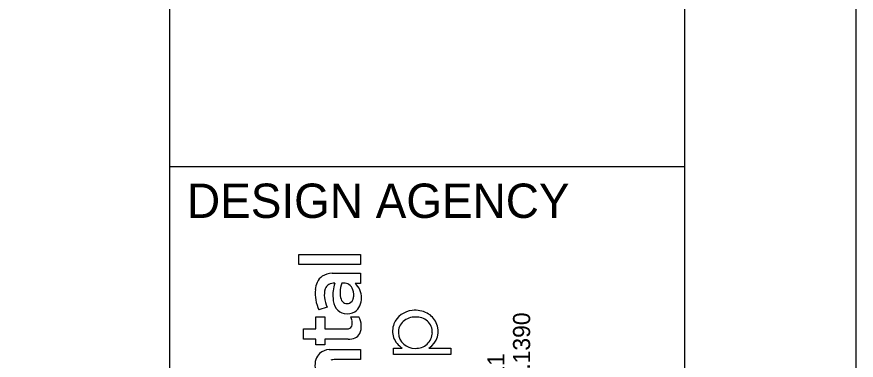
# Model space of a CAD drawing. Extents: x -5960 to 34, y -2569 to 22.
# Drawn here: x 31.554 to 34, y 3.936 to 4.936 of the extents above; entities that cross this region are included whole.
import ezdxf

# ---------------------------------------------------------------- set-up
doc = ezdxf.new("R2010")
doc.units = 0
for name, color, linetype in [('GT_Instrumented_Soil_Boring', 7, 'Continuous'), ('SV_X_Mon_Cells_Found', 7, 'Continuous'), ('SV_X_Shot_Marker', 7, 'Continuous')]:
    doc.layers.add(name, color=color, linetype=linetype)

msp = doc.modelspace()

# ---------------------------------------------------------------- linework, layer by layer
at = {"layer": 'GT_Instrumented_Soil_Boring'}
for p, q in [((32.3756, 4.2141), (32.3756, 4.244)), ((32.3756, 4.244), (32.5557, 4.244)), ((32.5557, 4.244), (32.5557, 4.2141)), ((32.5557, 4.2141), (32.3756, 4.2141)), ((32.4727, 4.189), (32.5555, 4.1892)), ((32.5555, 4.1892), (32.5557, 4.1596)), ((32.5557, 4.1596), (32.5397, 4.1596)), ((32.4582, 4.0904), (32.4343, 4.0823)), ((32.4254, 4.027), (32.4255, 4.0621)), ((32.4255, 4.0621), (32.4511, 4.0621)), ((32.4511, 4.0621), (32.4512, 4.027)), ((32.527, 4.0616), (32.5511, 4.0616)), ((32.3896, 3.9972), (32.3896, 4.027)), ((32.3896, 4.027), (32.4254, 4.027)), ((32.4512, 4.027), (32.515, 4.027)), ((32.515, 4.027), (32.52, 4.0275)), ((32.4254, 3.9972), (32.3896, 3.9972)), ((32.4254, 3.9807), (32.4254, 3.9972)), ((32.5197, 3.9972), (32.4511, 3.9972)), ((32.4511, 3.9972), (32.4511, 3.9807)), ((32.4511, 3.9807), (32.4254, 3.9807)), ((32.4644, 3.9669), (32.4729, 3.9673)), ((32.4729, 3.9673), (32.5557, 3.9673)), ((32.5557, 3.9673), (32.5557, 3.9375)), ((32.6515, 3.9521), (32.6515, 3.9711)), ((32.6515, 3.9711), (32.6771, 3.9711)), ((32.7549, 3.9713), (32.8186, 3.9711)), ((32.8186, 3.9711), (32.8184, 3.9521)), ((32.8184, 3.9521), (32.6515, 3.9521)), ((32.5557, 3.9375), (32.4814, 3.9375))]:
    msp.add_line(p, q, dxfattribs=at)
msp.add_lwpolyline([(32.3756, 4.2141), (32.3756, 4.244), (32.5557, 4.244), (32.5557, 4.2141)], close=True, dxfattribs=at)
for points in [[(32.4727, 4.189), (32.5555, 4.1892), (32.5557, 4.1596)], [(32.5557, 4.1596), (32.5397, 4.1596)], [(32.4582, 4.0904), (32.4343, 4.0823)], [(32.5197, 3.9972), (32.4511, 3.9972), (32.4511, 3.9807), (32.4254, 3.9807), (32.4254, 3.9972), (32.3896, 3.9972), (32.3896, 4.027), (32.4254, 4.027), (32.4255, 4.0621), (32.4511, 4.0621), (32.4512, 4.027), (32.515, 4.027), (32.52, 4.0275)], [(32.527, 4.0616), (32.5511, 4.0616)], [(32.4644, 3.9669), (32.4729, 3.9673), (32.5557, 3.9673), (32.5557, 3.9375), (32.4814, 3.9375)], [(32.7549, 3.9713), (32.8186, 3.9711), (32.8184, 3.9521), (32.6515, 3.9521)], [(32.6515, 3.9521), (32.6515, 3.9711), (32.6771, 3.9711)]]:
    msp.add_lwpolyline(points, dxfattribs=at)
for centre, radius, start, end in [((32.4745, 4.1326), 0.0565, 91.8942, 122.6317), ((32.4745, 4.1326), 0.0565, 91.8942, 122.6317), ((32.4882, 4.1361), 0.0646, 155.9764, 175.3149), ((32.4882, 4.1361), 0.0646, 155.9764, 175.3149), ((32.4685, 4.1447), 0.043, 124.537, 155.6594), ((32.4685, 4.1447), 0.043, 124.537, 155.6594), ((32.4779, 4.1278), 0.0321, 85.3802, 116.6222), ((32.4779, 4.1278), 0.0321, 85.3802, 116.6222), ((32.5879, 4.1251), 0.1129, 162.0821, 184.5285), ((32.5879, 4.1251), 0.1129, 162.0821, 184.5285), ((32.5801, 4.1313), 0.0841, 159.8366, 178.0362), ((32.5801, 4.1313), 0.0841, 159.8366, 178.0362), ((32.5051, 4.1074), 0.053, 79.6696, 94.2322), ((32.5051, 4.1074), 0.053, 79.6696, 94.2322), ((32.5089, 4.1364), 0.0238, 56.8913, 76.2149), ((32.5089, 4.1364), 0.0238, 56.8913, 76.2149), ((32.5055, 4.1191), 0.0529, 358.0746, 49.762), ((32.5055, 4.1191), 0.0529, 358.0746, 49.762), ((32.5364, 4.1308), 0.113, 174.6101, 205.3899), ((32.5364, 4.1308), 0.113, 174.6101, 205.3899), ((32.5076, 4.1265), 0.0576, 163.1369, 188.1675), ((32.5076, 4.1265), 0.0576, 163.1369, 188.1675), ((32.4753, 4.1356), 0.024, 119.4252, 161.6629), ((32.4753, 4.1356), 0.024, 119.4252, 161.6629), ((32.5466, 4.1303), 0.0506, 175.5903, 199.8857), ((32.5466, 4.1303), 0.0506, 175.5903, 199.8857), ((32.5052, 4.1318), 0.0297, 17.5984, 55.7282), ((32.5052, 4.1318), 0.0297, 17.5984, 55.7282), ((32.4916, 4.1264), 0.0443, 345.9408, 18.9919), ((32.4916, 4.1264), 0.0443, 345.9408, 18.9919), ((32.5473, 4.1297), 0.0973, 186.7598, 203.7981), ((32.5473, 4.1297), 0.0973, 186.7598, 203.7981), ((32.5328, 4.1187), 0.0575, 182.5676, 213.7144), ((32.5328, 4.1187), 0.0575, 182.5676, 213.7144), ((32.5164, 4.1189), 0.0184, 198.2844, 293.3081), ((32.5164, 4.1189), 0.0184, 198.2844, 293.3081), ((32.5152, 4.1199), 0.0199, 295.2883, 347.4639), ((32.5152, 4.1199), 0.0199, 295.2883, 347.4639), ((32.5019, 4.1168), 0.0566, 336.016, 0.5951), ((32.5019, 4.1168), 0.0566, 336.016, 0.5951), ((32.5149, 4.1078), 0.0366, 215.0668, 259.8133), ((32.5149, 4.1078), 0.0366, 215.0668, 259.8133), ((32.5175, 4.1097), 0.0394, 303.4436, 336.18), ((32.5175, 4.1097), 0.0394, 303.4436, 336.18), ((32.5175, 4.1131), 0.0423, 257.5256, 300.882), ((32.5175, 4.1131), 0.0423, 257.5256, 300.882), ((32.4863, 4.042), 0.0452, 10.1545, 25.723), ((32.4863, 4.042), 0.0452, 10.1545, 25.723), ((32.503, 4.0351), 0.0549, 336.589, 28.8991), ((32.503, 4.0351), 0.0549, 336.589, 28.8991), ((32.7108, 4.0182), 0.0624, 93.9866, 158.3119), ((32.7108, 4.0182), 0.0624, 93.9866, 158.3119), ((32.7138, 4.0102), 0.0513, 87.8965, 131.1812), ((32.7138, 4.0102), 0.0513, 87.8965, 131.1812), ((32.7156, 4.0065), 0.0746, 62.6889, 97.0135), ((32.7156, 4.0065), 0.0746, 62.6889, 97.0135), ((32.7175, 4.0102), 0.0513, 49.9089, 92.0363), ((32.7175, 4.0102), 0.0513, 49.9089, 92.0363), ((32.7212, 4.0191), 0.0608, 25.0657, 61.9602), ((32.7212, 4.0191), 0.0608, 25.0657, 61.9602), ((32.5184, 4.04), 0.0126, 277.6142, 353.7918), ((32.5184, 4.04), 0.0126, 277.6142, 353.7918), ((32.4957, 4.0436), 0.0356, 351.914, 10.2059), ((32.4957, 4.0436), 0.0356, 351.914, 10.2059), ((32.707, 4.0202), 0.0581, 158.656, 198.171), ((32.707, 4.0202), 0.0581, 158.656, 198.171), ((32.7092, 4.0167), 0.0434, 132.3289, 182.0949), ((32.7092, 4.0167), 0.0434, 132.3289, 182.0949), ((32.7215, 4.0173), 0.0433, 358.0487, 47.9447), ((32.7215, 4.0173), 0.0433, 358.0487, 47.9447), ((32.7245, 4.02), 0.0574, 301.9776, 25.6418), ((32.7245, 4.02), 0.0574, 301.9776, 25.6418), ((32.5291, 4.0261), 0.0275, 292.6889, 332.0598), ((32.5291, 4.0261), 0.0275, 292.6889, 332.0598), ((32.7135, 4.0181), 0.0478, 183.5974, 271.7045), ((32.7135, 4.0181), 0.0478, 183.5974, 271.7045), ((32.7172, 4.018), 0.0477, 267.3149, 357.4019), ((32.7172, 4.018), 0.0477, 267.3149, 357.4019), ((32.5209, 4.0486), 0.0514, 268.6727, 291.5235), ((32.5209, 4.0486), 0.0514, 268.6727, 291.5235), ((32.7103, 4.0243), 0.0627, 200.8399, 238.0162), ((32.7103, 4.0243), 0.0627, 200.8399, 238.0162), ((32.4687, 3.9172), 0.0499, 94.9706, 130.2248), ((32.4687, 3.9172), 0.0499, 94.9706, 130.2248), ((32.4635, 3.9255), 0.0402, 132.2238, 161.6823), ((32.4635, 3.9255), 0.0402, 132.2238, 161.6823), ((32.4787, 3.9211), 0.056, 162.274, 187.7917), ((32.4787, 3.9211), 0.056, 162.274, 187.7917), ((32.4811, 3.8915), 0.046, 89.6051, 105.3303), ((32.4811, 3.8915), 0.046, 89.6051, 105.3303)]:
    msp.add_arc(centre, radius, start, end, dxfattribs=at)
at = {"layer": 'SV_X_Mon_Cells_Found'}
msp.add_lwpolyline([(0, 0), (34, 0), (34, 22), (0, 22)], close=True, dxfattribs=at)
at = {"layer": 'SV_X_Shot_Marker'}
for p, q in [((32, 0.5), (32, 21.5)), ((32, 4.5), (33.5, 4.5))]:
    msp.add_line(p, q, dxfattribs=at)
msp.add_lwpolyline([(1.5, 21.5), (33.5, 21.5), (33.5, 0.5), (1.5, 0.5)], close=True, dxfattribs=at)

# ---------------------------------------------------------------- texts
at = {"layer": 'GT_Instrumented_Soil_Boring'}
msp.add_text('DESIGN AGENCY', height=0.1, dxfattribs=at).set_placement((32.05, 4.35))
for s, p in [('800.835.1390', (33.0497, 3.6671)), ('450 GRANT ST., AKRON, OH  44311', (32.9749, 2.8374))]:
    msp.add_text(s, height=0.049846, rotation=90, dxfattribs=at).set_placement(p)

doc.saveas('drawing.dxf')
